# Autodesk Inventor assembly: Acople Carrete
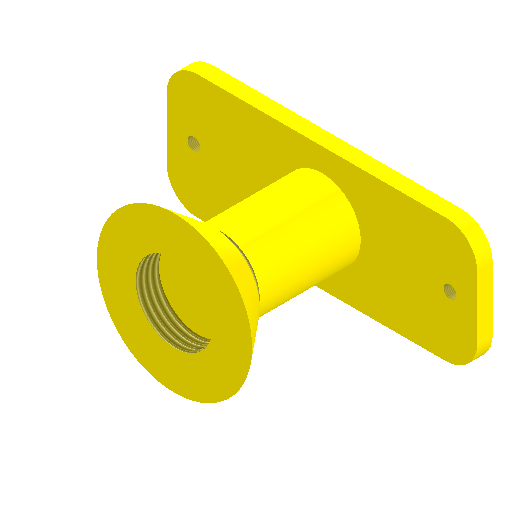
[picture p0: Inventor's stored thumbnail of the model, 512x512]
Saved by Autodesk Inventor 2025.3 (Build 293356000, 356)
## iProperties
Created: 2026-01
Part Number: Acople Carrete
Document SubType Name: Assembly
Designer: Dell
Author: Dell
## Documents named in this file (3)
- C:\Users\Dell\Downloads\TESIS FINAL\CAD Final\Acople Carrete.iam
- C:\Users\Dell\Downloads\TESIS FINAL\CAD Final\Acople_PLA.ipt
- C:\Users\Dell\Downloads\TESIS FINAL\CAD Final\Tapa_Carrete.ipt
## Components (2 placed, 2 different names)
1. Acople_PLA:1 — Insertar:1
2. Tapa_Carrete:1 — Insertar:1
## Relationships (1: Insert 1)
- Insertar:1: Acople_PLA:1 ↔ Tapa_Carrete:1
